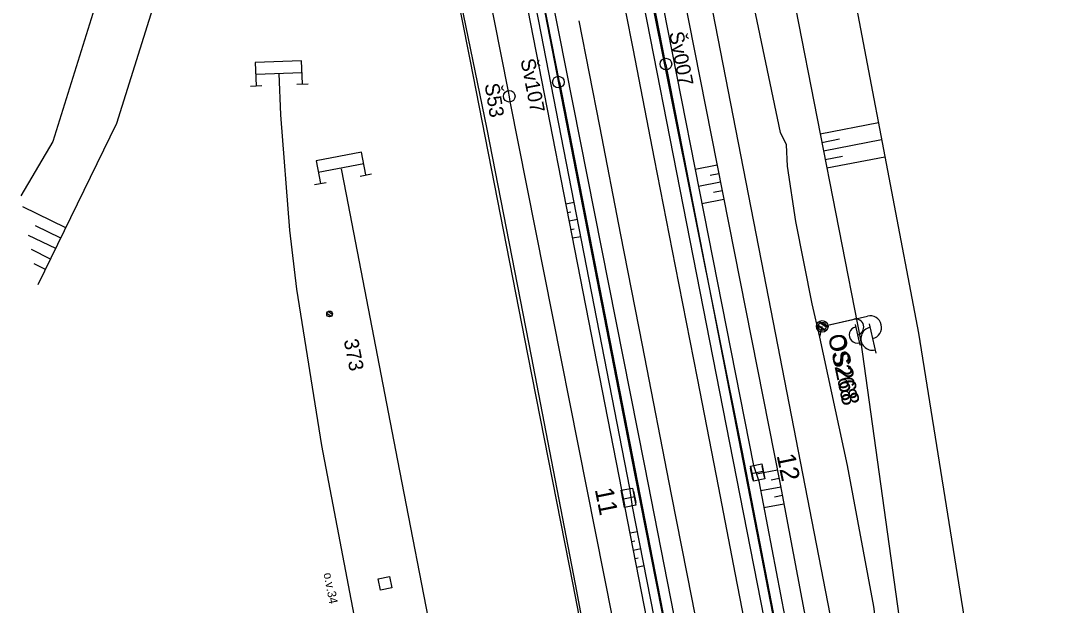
# Model space of a CAD drawing. Extents: x -545967 to -545044, y -1122650 to -1118491.
# Drawn here: x -545860.7 to -545770.8, y -1118760.6 to -1118710.2 of the extents above; entities that cross this region are included whole.
import ezdxf

# ---------------------------------------------------------------- set-up
doc = ezdxf.new("R2010")
doc.units = 0
for name, color, linetype in [('Vrstva 1', 7, 'Continuous'), ('Vrstva 1 - Koleje', 7, 'Continuous'), ('Vrstva 11', 7, 'Continuous'), ('Vrstva 11 - Trakce', 7, 'Continuous'), ('Vrstva 12 - Trakce zaklady', 7, 'Continuous'), ('Vrstva 15_zarazedla', 7, 'Continuous'), ('Vrstva 25', 7, 'Continuous'), ('Vrstva 25 - silnoproud prvky', 7, 'Continuous'), ('Vrstva 26', 7, 'Continuous'), ('Vrstva 26 - silnoproud', 7, 'Continuous'), ('Vrstva 28 - zabzar', 7, 'Continuous'), ('Vrstva 32', 7, 'Continuous'), ('Vrstva 4 - Teren - stezky - prechody - plochy', 7, 'Continuous'), ('Vrstva 43', 7, 'Continuous'), ('Vrstva 44', 7, 'Continuous'), ('Vrstva 48', 7, 'Continuous'), ('Vrstva 49', 7, 'Continuous'), ('Vrstva 62', 7, 'Continuous')]:
    doc.layers.add(name, color=color, linetype=linetype)

msp = doc.modelspace()

# ---------------------------------------------------------------- linework, layer by layer
at = {"layer": 'Vrstva 1'}
for points in [[(-545803.343, -1118697.361), (-545802.529, -1118701.559), (-545796.372, -1118733.137), (-545788.892, -1118771.626), (-545784.123, -1118796.192), (-545777.723, -1118829.089), (-545771.163, -1118862.699), (-545764.792, -1118895.381), (-545757.603, -1118932.309), (-545753.441, -1118953.648), (-545749.904, -1118971.286), (-545746.403, -1118987.4), (-545742.64, -1119003.664), (-545739.307, -1119017.411), (-545735.997, -1119030.103), (-545730.526, -1119049.438)], [(-545838.408, -1118714.766), (-545838.264, -1118718.348), (-545837.486, -1118728.28), (-545836.887, -1118733.389), (-545834.73, -1118746.875), (-545830.836, -1118767.188), (-545826.73, -1118788.319), (-545823.138, -1118806.831), (-545818.076, -1118832.894), (-545813.108, -1118858.452), (-545808.531, -1118881.987), (-545803.057, -1118910.121), (-545797.597, -1118938.248), (-545792.143, -1118966.396), (-545787.423, -1118990.652), (-545782.57, -1119015.553), (-545777.212, -1119042.997), (-545771.689, -1119071.297)], [(-545838.408, -1118714.766), (-545838.264, -1118718.348), (-545837.486, -1118728.28), (-545836.887, -1118733.389), (-545834.73, -1118746.875), (-545830.836, -1118767.188), (-545826.73, -1118788.319), (-545823.138, -1118806.831), (-545818.076, -1118832.894), (-545813.108, -1118858.452), (-545808.531, -1118881.987), (-545803.057, -1118910.121), (-545797.597, -1118938.248), (-545792.143, -1118966.396), (-545787.423, -1118990.652), (-545782.57, -1119015.553), (-545777.212, -1119042.997), (-545771.689, -1119071.297)], [(-545833.035, -1118722.987), (-545832.612, -1118725.218), (-545828.16, -1118748.155), (-545821.787, -1118781.064), (-545814.8, -1118816.973), (-545807.184, -1118856.232), (-545801.349, -1118886.259), (-545795.986, -1118913.812), (-545789.887, -1118945.221), (-545784.095, -1118975.016), (-545776.352, -1119014.883), (-545771.025, -1119042.195)]]:
    msp.add_lwpolyline(points, dxfattribs=at)
at = {"layer": 'Vrstva 1 - Koleje'}
for points in [[(-545809.67, -1118703.454), (-545807.882, -1118712.632), (-545806.03, -1118722.125), (-545804.223, -1118731.391), (-545802.337, -1118741.068), (-545800.493, -1118750.516), (-545799.063, -1118757.843), (-545797.222, -1118767.299), (-545795.407, -1118776.622), (-545793.591, -1118785.937), (-545791.761, -1118795.345), (-545790.039, -1118804.177), (-545787.497, -1118817.223), (-545785.692, -1118826.488), (-545783.856, -1118835.888), (-545781.902, -1118845.893)], [(-545812.52, -1118710.222), (-545810.747, -1118719.317), (-545808.924, -1118728.683), (-545807.065, -1118738.215), (-545804.558, -1118751.082), (-545802.792, -1118760.131), (-545800.853, -1118770.074), (-545799.124, -1118778.962), (-545797.814, -1118785.665), (-545796.111, -1118794.424), (-545793.992, -1118805.28), (-545790.937, -1118820.957), (-545789.005, -1118830.866), (-545787.094, -1118840.68)]]:
    msp.add_lwpolyline(points, dxfattribs=at)
at = {"layer": 'Vrstva 11'}
for p, q in [((-545833.895, -1118735.732), (-545834.273, -1118735.476)), ((-545833.787, -1118735.578), (-545834.171, -1118735.319))]:
    msp.add_line(p, q, dxfattribs=at)
msp.add_circle((-545834.029, -1118735.523), 0.25, dxfattribs=at)
at = {"layer": 'Vrstva 11 - Trakce'}
for p, q in [((-545797.738, -1118748.826), (-545797.536, -1118749.806)), ((-545796.657, -1118749.114), (-545797.637, -1118749.316)), ((-545796.758, -1118748.624), (-545796.556, -1118749.604)), ((-545808.785, -1118750.993), (-545808.592, -1118751.974)), ((-545807.804, -1118750.8), (-545807.611, -1118751.781)), ((-545807.707, -1118751.29), (-545808.689, -1118751.484))]:
    msp.add_line(p, q, dxfattribs=at)
at = {"layer": 'Vrstva 12 - Trakce zaklady'}
for p, q in [((-545797.725, -1118748.66), (-545796.746, -1118748.458)), ((-545796.48, -1118749.75), (-545797.459, -1118749.952)), ((-545808.872, -1118750.732), (-545807.891, -1118750.538)), ((-545807.6, -1118752.01), (-545808.581, -1118752.204))]:
    msp.add_line(p, q, dxfattribs=at)
for points in [[(-545797.459, -1118749.952), (-545797.725, -1118748.66), (-545796.746, -1118748.458), (-545796.48, -1118749.75), (-545797.459, -1118749.952)], [(-545797.725, -1118748.66), (-545797.725, -1118748.66), (-545797.459, -1118749.952), (-545797.459, -1118749.952)], [(-545796.746, -1118748.458), (-545796.746, -1118748.458), (-545796.48, -1118749.75), (-545796.48, -1118749.75)], [(-545807.891, -1118750.538), (-545807.6, -1118752.01), (-545808.581, -1118752.204), (-545808.872, -1118750.732), (-545807.891, -1118750.538)], [(-545808.872, -1118750.732), (-545808.872, -1118750.732), (-545808.581, -1118752.204), (-545808.581, -1118752.204)], [(-545807.891, -1118750.538), (-545807.891, -1118750.538), (-545807.6, -1118752.01), (-545807.6, -1118752.01)]]:
    msp.add_lwpolyline(points, dxfattribs=at)
at = {"layer": 'Vrstva 15_zarazedla'}
for p, q in [((-545840.406, -1118714.837), (-545836.41, -1118714.677)), ((-545840.866, -1118715.856), (-545839.867, -1118715.816)), ((-545836.869, -1118715.696), (-545835.87, -1118715.656)), ((-545835.014, -1118723.289), (-545831.084, -1118722.543)), ((-545831.389, -1118723.619), (-545830.406, -1118723.432)), ((-545835.319, -1118724.365), (-545834.336, -1118724.178))]:
    msp.add_line(p, q, dxfattribs=at)
for points in [[(-545836.369, -1118715.676), (-545836.45, -1118713.678), (-545840.447, -1118713.838), (-545840.366, -1118715.836)], [(-545830.898, -1118723.526), (-545831.27, -1118721.561), (-545835.2, -1118722.306), (-545834.828, -1118724.271)]]:
    msp.add_lwpolyline(points, dxfattribs=at)
at = {"layer": 'Vrstva 25'}
for p, q in [((-545791.05, -1118736.481), (-545787.639, -1118735.697)), ((-545792.016, -1118736.458), (-545791.205, -1118736.966)), ((-545791.786, -1118736.16), (-545791.041, -1118736.627)), ((-545787.482, -1118736.379), (-545786.899, -1118738.913))]:
    msp.add_line(p, q, dxfattribs=at)
msp.add_lwpolyline([(-545829.645, -1118759.344), (-545829.837, -1118758.362), (-545828.855, -1118758.17), (-545828.663, -1118759.152)], close=True, dxfattribs=at)
msp.add_circle((-545791.537, -1118736.593), 0.5, dxfattribs=at)
msp.add_circle((-545791.537, -1118736.593), 0.5, dxfattribs=at)
for centre, start, end in [((-545787.415, -1118736.671), 282.94955, 102.94955), ((-545787.202, -1118737.649), 102.24698, 283.65212)]:
    msp.add_arc(centre, 1, start, end, dxfattribs=at)
at = {"layer": 'Vrstva 25 - silnoproud prvky'}
for p, q in [((-545791.873, -1118736.499), (-545791.305, -1118736.854)), ((-545791.712, -1118736.29), (-545791.19, -1118736.617)), ((-545791.196, -1118736.515), (-545788.808, -1118735.966)), ((-545788.698, -1118736.443), (-545788.291, -1118738.217))]:
    msp.add_line(p, q, dxfattribs=at)
msp.add_circle((-545791.537, -1118736.593), 0.35, dxfattribs=at)
for centre, start, end in [((-545788.503, -1118737.332), 102.24698, 283.65212), ((-545788.651, -1118736.648), 282.94955, 102.94955)]:
    msp.add_arc(centre, 0.7, start, end, dxfattribs=at)
at = {"layer": 'Vrstva 26'}
for points in [[(-545771.097, -1118840.383), (-545773.141, -1118830.925), (-545777.672, -1118810.574), (-545780.401, -1118795.417), (-545781.883, -1118790.167), (-545782.61, -1118786.576), (-545783.878, -1118776.094), (-545784.515, -1118772.9), (-545785.804, -1118770.659), (-545787.081, -1118760.752), (-545789.369, -1118748.588), (-545791.737, -1118737.523), (-545792.399, -1118734.644), (-545793.816, -1118727.544), (-545794.532, -1118722.759), (-545794.625, -1118720.933), (-545795.14, -1118719.856), (-545797.401, -1118709.038)], [(-545791.737, -1118737.523), (-545791.537, -1118736.593)]]:
    msp.add_lwpolyline(points, dxfattribs=at)
at = {"layer": 'Vrstva 26 - silnoproud'}
for points in [[(-545804.723, -1118669.38), (-545823.422, -1118673.004), (-545824.024, -1118671.607), (-545826.19, -1118672.019), (-545826.479, -1118672.345), (-545826.082, -1118675.405), (-545825.636, -1118675.016), (-545825.253, -1118675.052), (-545825.524, -1118675.387), (-545825.985, -1118675.439), (-545827.078, -1118675.764), (-545828.843, -1118676.437), (-545828.656, -1118678.804), (-545827.868, -1118683.721), (-545826.321, -1118691.367), (-545821.946, -1118713.57), (-545816.92, -1118739.132), (-545813.046, -1118758.857), (-545808.289, -1118783.504), (-545803.049, -1118810.067), (-545800.897, -1118821.514), (-545796.684, -1118843.318)], [(-545771.097, -1118840.383), (-545773.141, -1118830.925), (-545777.672, -1118810.574), (-545780.401, -1118795.417), (-545781.883, -1118790.167), (-545782.61, -1118786.576), (-545783.878, -1118776.094), (-545784.515, -1118772.9), (-545785.804, -1118770.659), (-545787.081, -1118760.752), (-545789.369, -1118748.588), (-545791.737, -1118737.523), (-545792.399, -1118734.644), (-545793.816, -1118727.544), (-545794.532, -1118722.759), (-545794.625, -1118720.933), (-545795.14, -1118719.856), (-545797.401, -1118709.038)], [(-545791.737, -1118737.523), (-545791.537, -1118736.593)]]:
    msp.add_lwpolyline(points, dxfattribs=at)
at = {"layer": 'Vrstva 28 - zabzar'}
msp.add_lwpolyline([(-545759.72, -1119031.91), (-545759.89, -1119030.77), (-545763.23, -1119013.33), (-545766.25, -1118997.62), (-545768.86, -1118984.55), (-545771, -1118974.69), (-545771.8, -1118970.9), (-545773.86, -1118959.07), (-545776.3, -1118946.17), (-545780.31, -1118924.98), (-545785.87, -1118897.11), (-545790.99, -1118870.65), (-545796.29, -1118843.25), (-545799.19, -1118827.63), (-545805.85, -1118794.17), (-545808.2, -1118783.5), (-545812.82, -1118758.82), (-545816.62, -1118739.16), (-545820.43, -1118719.58), (-545822.89, -1118707.67), (-545825.23, -1118696.09)], dxfattribs=at)
at = {"layer": 'Vrstva 32'}
msp.add_lwpolyline([(-545796.29, -1118843.25), (-545799.19, -1118827.63), (-545805.85, -1118794.17), (-545808.2, -1118783.5), (-545812.82, -1118758.82), (-545816.62, -1118739.16), (-545820.43, -1118719.58), (-545822.89, -1118707.67)], dxfattribs=at)
at = {"layer": 'Vrstva 4 - Teren - stezky - prechody - plochy'}
for points in [[(-545842.057, -1118523.737), (-545841.08, -1118528.803), (-545840.285, -1118532.869), (-545839.902, -1118534.493), (-545835.95, -1118554.692), (-545830.173, -1118584.852), (-545827.402, -1118599.381), (-545819.669, -1118640.626), (-545818.68, -1118644.829), (-545817.556, -1118652.409), (-545817.153, -1118653.253), (-545814.795, -1118664.646), (-545810.716, -1118686.202), (-545798.466, -1118747.292), (-545787.709, -1118802.92), (-545777.141, -1118857.583)], [(-545842.991, -1118523.919), (-545841.705, -1118530.396), (-545836.849, -1118554.447), (-545831.054, -1118584.604), (-545819.351, -1118645.264), (-545811.232, -1118686.911), (-545799.532, -1118746.647), (-545788.535, -1118802.768), (-545777.847, -1118857.696), (-545765.826, -1118919.341), (-545755.98, -1118970.183), (-545745.509, -1119023.121), (-545734.813, -1119078.883), (-545723.148, -1119138.675), (-545711.327, -1119199.256), (-545707.51, -1119218.932), (-545706.355, -1119218.803)], [(-545711.324, -1119247.435), (-545711.901, -1119243.963), (-545720.224, -1119201.665), (-545721.285, -1119195.757), (-545731.546, -1119141.712), (-545737.081, -1119112.42), (-545743.441, -1119079.103), (-545754.278, -1119022.005), (-545764.127, -1118971.243), (-545774.702, -1118917.119), (-545786.098, -1118858.181), (-545797.005, -1118803.413), (-545807.661, -1118749.422), (-545819.911, -1118686.431), (-545828.531, -1118641.36), (-545850.15, -1118530.525), (-545851.156, -1118525.517)], [(-545710.225, -1119247.22), (-545719.004, -1119201.386), (-545730.622, -1119141.385), (-545736.208, -1119112.206), (-545742.564, -1119078.927), (-545753.414, -1119021.814), (-545763.359, -1118970.942), (-545773.922, -1118916.709), (-545785.328, -1118858.188), (-545796.206, -1118802.914), (-545806.845, -1118748.63), (-545819.206, -1118686.191), (-545827.818, -1118641.013), (-545849.345, -1118530.249), (-545850.409, -1118525.371)]]:
    msp.add_lwpolyline(points, dxfattribs=at)
at = {"layer": 'Vrstva 43'}
for centre in [(-545805.018, -1118713.963), (-545814.298, -1118715.518), (-545818.53, -1118716.741)]:
    msp.add_circle(centre, 0.5, dxfattribs=at)
at = {"layer": 'Vrstva 44'}
for points in [[(-545846.223, -1118571.979), (-545846.221, -1118572.119), (-545836.892, -1118620.467), (-545827.979, -1118669.157), (-545827.809, -1118669.462), (-545827.871, -1118669.728), (-545818.616, -1118716.33), (-545818.55, -1118716.796), (-545818.473, -1118717.196), (-545808.913, -1118765.432), (-545808.826, -1118765.882), (-545808.745, -1118766.383), (-545799.375, -1118814.752), (-545799.301, -1118815.001), (-545799.29, -1118815.321), (-545789.933, -1118863.748)], [(-545805.038, -1118714.002), (-545814.588, -1118665.112)], [(-545814.194, -1118715.513), (-545823.815, -1118666.664), (-545823.785, -1118666.525)], [(-545805.038, -1118714.002), (-545795.436, -1118763.417), (-545804.505, -1118764.688), (-545804.688, -1118764.766)], [(-545814.194, -1118715.513), (-545804.66, -1118764.526), (-545804.688, -1118764.766)]]:
    msp.add_lwpolyline(points, dxfattribs=at)
at = {"layer": 'Vrstva 48'}
for p, q in [((-545791.703, -1118719.984), (-545786.693, -1118719.005)), ((-545791.559, -1118720.72), (-545790.057, -1118720.427)), ((-545791.415, -1118721.456), (-545786.412, -1118720.479)), ((-545791.271, -1118722.192), (-545789.772, -1118721.899)), ((-545791.128, -1118722.928), (-545786.132, -1118721.952)), ((-545800.601, -1118722.694), (-545802.487, -1118723.067)), ((-545800.455, -1118723.43), (-545801.21, -1118723.579)), ((-545800.31, -1118724.165), (-545802.197, -1118724.539)), ((-545800.164, -1118724.901), (-545800.919, -1118725.051)), ((-545813.642, -1118726.019), (-545812.944, -1118725.882)), ((-545800.019, -1118725.637), (-545801.907, -1118726.01)), ((-545813.499, -1118726.755), (-545813.219, -1118726.7)), ((-545813.355, -1118727.491), (-545812.657, -1118727.355)), ((-545813.211, -1118728.227), (-545812.932, -1118728.173)), ((-545813.067, -1118728.963), (-545812.37, -1118728.827)), ((-545795.401, -1118748.983), (-545797.206, -1118749.34)), ((-545795.256, -1118749.718), (-545795.944, -1118749.855)), ((-545795.112, -1118750.455), (-545796.84, -1118750.78)), ((-545794.835, -1118751.929), (-545796.558, -1118752.254)), ((-545794.974, -1118751.192), (-545795.664, -1118751.322)), ((-545808.11, -1118754.411), (-545807.467, -1118754.285)), ((-545807.966, -1118755.147), (-545807.709, -1118755.097)), ((-545807.822, -1118755.883), (-545807.178, -1118755.757)), ((-545807.678, -1118756.619), (-545807.421, -1118756.569)), ((-545807.535, -1118757.355), (-545806.889, -1118757.229))]:
    msp.add_line(p, q, dxfattribs=at)
at = {"layer": 'Vrstva 49'}
for points in [[(-545841.458, -1118523.619), (-545840.502, -1118528.796), (-545840.206, -1118530.169), (-545839.525, -1118532.718), (-545839.264, -1118534.264), (-545835.124, -1118554.723), (-545829.514, -1118584.885), (-545827.92, -1118592.873), (-545827.648, -1118594.262), (-545826.635, -1118599.217), (-545819.032, -1118640.374), (-545818.68, -1118644.829), (-545817.556, -1118652.409), (-545816.515, -1118653.065), (-545813.954, -1118664.567), (-545810.048, -1118684.976), (-545808.757, -1118691.228), (-545797.462, -1118748.583), (-545796.998, -1118749.953), (-545786.899, -1118802.732), (-545785.57, -1118809.023), (-545776.461, -1118857.744)], [(-545839.308, -1118523.198), (-545838.102, -1118529.579), (-545837.4, -1118533.485), (-545832.706, -1118555.695), (-545825.144, -1118594.377), (-545814.251, -1118651.352), (-545808.026, -1118685.152), (-545795.162, -1118750.192), (-545783.943, -1118809.71), (-545774.848, -1118856.951), (-545763.418, -1118915.038), (-545752.928, -1118968.655), (-545741.707, -1119025.946), (-545730.219, -1119081.986), (-545719.001, -1119141.326), (-545708.857, -1119196.833), (-545704.642, -1119214.146)], [(-545787.565, -1118859.78), (-545796.822, -1118811.001), (-545797.303, -1118809.619), (-545797.956, -1118806.406), (-545798.235, -1118804.969), (-545808.533, -1118752.244), (-545808.823, -1118750.705), (-545820.011, -1118693.395), (-545820.267, -1118691.79), (-545820.94, -1118688.496), (-545821.249, -1118687.074), (-545823.077, -1118678.082), (-545823.606, -1118676.864), (-545824.251, -1118676.389)], [(-545786.924, -1118859.548), (-545796.323, -1118810.897), (-545796.625, -1118809.56), (-545797.25, -1118806.278), (-545797.544, -1118804.841), (-545807.893, -1118752.116), (-545808.138, -1118750.544), (-545819.301, -1118693.257), (-545819.514, -1118691.615), (-545820.246, -1118688.348), (-545820.472, -1118686.892), (-545821.991, -1118678.267), (-545823.152, -1118676.433), (-545824.251, -1118676.389)], [(-545790.558, -1118698.682), (-545783.238, -1118737.17), (-545773.95, -1118795.15), (-545740.894, -1118934.351)], [(-545795.7, -1118699.528), (-545788.233, -1118737.742), (-545783.17, -1118774.198), (-545777.676, -1118791.958), (-545766.252, -1118834.896), (-545762.229, -1118863.517), (-545750.538, -1118910.15), (-545748.755, -1118933.679), (-545738.226, -1118978.242), (-545734.453, -1118993.366), (-545726.802, -1119029.271), (-545708.682, -1119069.733), (-545699.17, -1119099.963), (-545685.313, -1119124.181), (-545683.358, -1119136.056), (-545688.074, -1119145.796), (-545688.341, -1119153.091)]]:
    msp.add_lwpolyline(points, dxfattribs=at)
at = {"layer": 'Vrstva 62'}
for points in [[(-545851.998, -1118701.747), (-545857.899, -1118720.647), (-545860.666, -1118725.342)], [(-545859.169, -1118732.989), (-545852.397, -1118719.074), (-545848.036, -1118705.198)], [(-545856.783, -1118728.085), (-545860.481, -1118726.285)], [(-545857.22, -1118728.984), (-545859.393, -1118727.927)], [(-545857.658, -1118729.883), (-545860, -1118728.743)], [(-545858.095, -1118730.782), (-545859.759, -1118729.972)], [(-545858.533, -1118731.681), (-545859.519, -1118731.201)]]:
    msp.add_lwpolyline(points, dxfattribs=at)

# ---------------------------------------------------------------- texts
at = {"layer": 'Vrstva 11'}
msp.add_text('373', height=1.25, rotation=281.02028, dxfattribs=at).set_placement((-545832.813, -1118737.791))
at = {"layer": 'Vrstva 11 - Trakce'}
for s, rotation, p in [('12', 281.63363, (-545795.473, -1118747.726)), ('11', 281.18263, (-545811.159, -1118750.653))]:
    msp.add_text(s, height=1.6, rotation=rotation, dxfattribs=at).set_placement(p)
at = {"layer": 'Vrstva 25'}
for s, height, rotation, p in [('OS268', 1.5, 282.07955, (-545791.045, -1118737.413)), ('o.v.34', 0.75, 281.042, (-545834.559, -1118757.905))]:
    msp.add_text(s, height=height, rotation=rotation, dxfattribs=at).set_placement(p)
at = {"layer": 'Vrstva 25 - silnoproud prvky'}
msp.add_text('OS268', height=1.4, rotation=282.07955, dxfattribs=at).set_placement((-545791.045, -1118737.413))
at = {"layer": 'Vrstva 43'}
for s, rotation, p in [('Šv007', 280.99979, (-545804.756, -1118711.276)), ('Šv107', 280.99979, (-545817.569, -1118713.603)), ('Š53', 279.31701, (-545820.665, -1118715.708))]:
    msp.add_text(s, height=1.25, rotation=rotation, dxfattribs=at).set_placement(p)

doc.saveas('drawing.dxf')
